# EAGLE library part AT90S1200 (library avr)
MICROCONTROLLER 1 Kbytes FLASH 64 bytes EEPROM
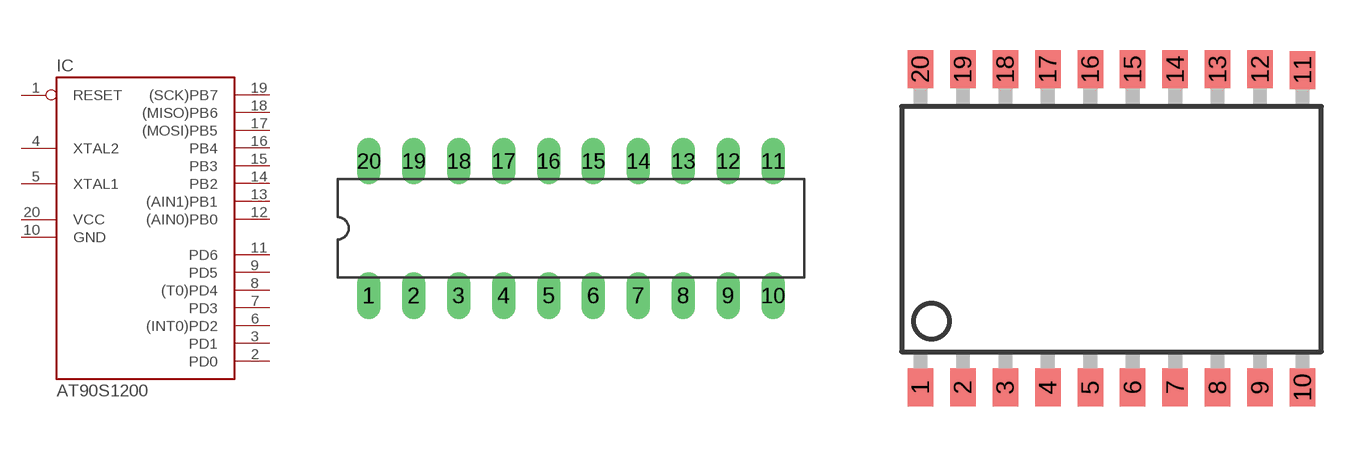
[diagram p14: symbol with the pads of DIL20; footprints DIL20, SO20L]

Designator prefix IC

## AT90S1200P  [DIL20]
1  RESET
2  PD0
3  PD1
4  XTAL2
5  XTAL1
6  (INT0)PD2
7  PD3
8  (T0)PD4
9  PD5
10  GND  pwr
11  PD6
12  (AIN0)PB0
13  (AIN1)PB1
14  PB2
15  PB3
16  PB4
17  (MOSI)PB5
18  (MISO)PB6
19  (SCK)PB7
20  VCC  pwr

## AT90S1200S  [SO20L]
Pads as for DIL20

## AT90S1200Y  [SSOP20D8]
Pads as for DIL20

## Footprint DIL20 (pad centres in mm)
Dual In Line
drill 0.813 long: 1 -11.43,-3.81; 2 -8.89,-3.81; 3 -6.35,-3.81; 4 -3.81,-3.81; 5 -1.27,-3.81; 6 1.27,-3.81; 7 3.81,-3.81; 8 6.35,-3.81; 9 8.89,-3.81; 10 11.43,-3.81; 11 11.43,3.81; 12 8.89,3.81; 13 6.35,3.81; 14 3.81,3.81; 15 1.27,3.81; 16 -1.27,3.81; 17 -3.81,3.81; 18 -6.35,3.81; 19 -8.89,3.81; 20 -11.43,3.81

## Footprint SO20L (pad centres in mm)
Small Outline Package
smd 0.762 x 1.143: 1 -5.08,-5.131; 2 -3.81,-5.131; 3 -2.54,-5.131; 4 -1.27,-5.131; 5 0,-5.131; 6 1.27,-5.131; 7 2.54,-5.131; 8 3.81,-5.131; 9 5.08,-5.131; 10 6.35,-5.131; 11 6.35,4.369; 12 5.08,4.394; 13 3.81,4.394; 14 2.54,4.394; 15 1.27,4.394; 16 0,4.394; 17 -1.27,4.394; 18 -2.54,4.394; 19 -3.81,4.394; 20 -5.08,4.394

## Footprint SSOP20D8 (pad centres in mm)
Plastic Shrink Small Outline Package
smd 0.305 x 1.245: 1 -2.794,-3.353; 2 -2.159,-3.353; 3 -1.524,-3.353; 4 -0.889,-3.353; 5 -0.254,-3.353; 6 0.381,-3.353; 7 1.016,-3.353; 8 1.651,-3.353; 9 2.286,-3.353; 10 2.921,-3.353; 11 2.921,3.251; 12 2.286,3.251; 13 1.651,3.251; 14 1.016,3.251; 15 0.381,3.251; 16 -0.254,3.251; 17 -0.889,3.251; 18 -1.524,3.251; 19 -2.159,3.251; 20 -2.794,3.251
